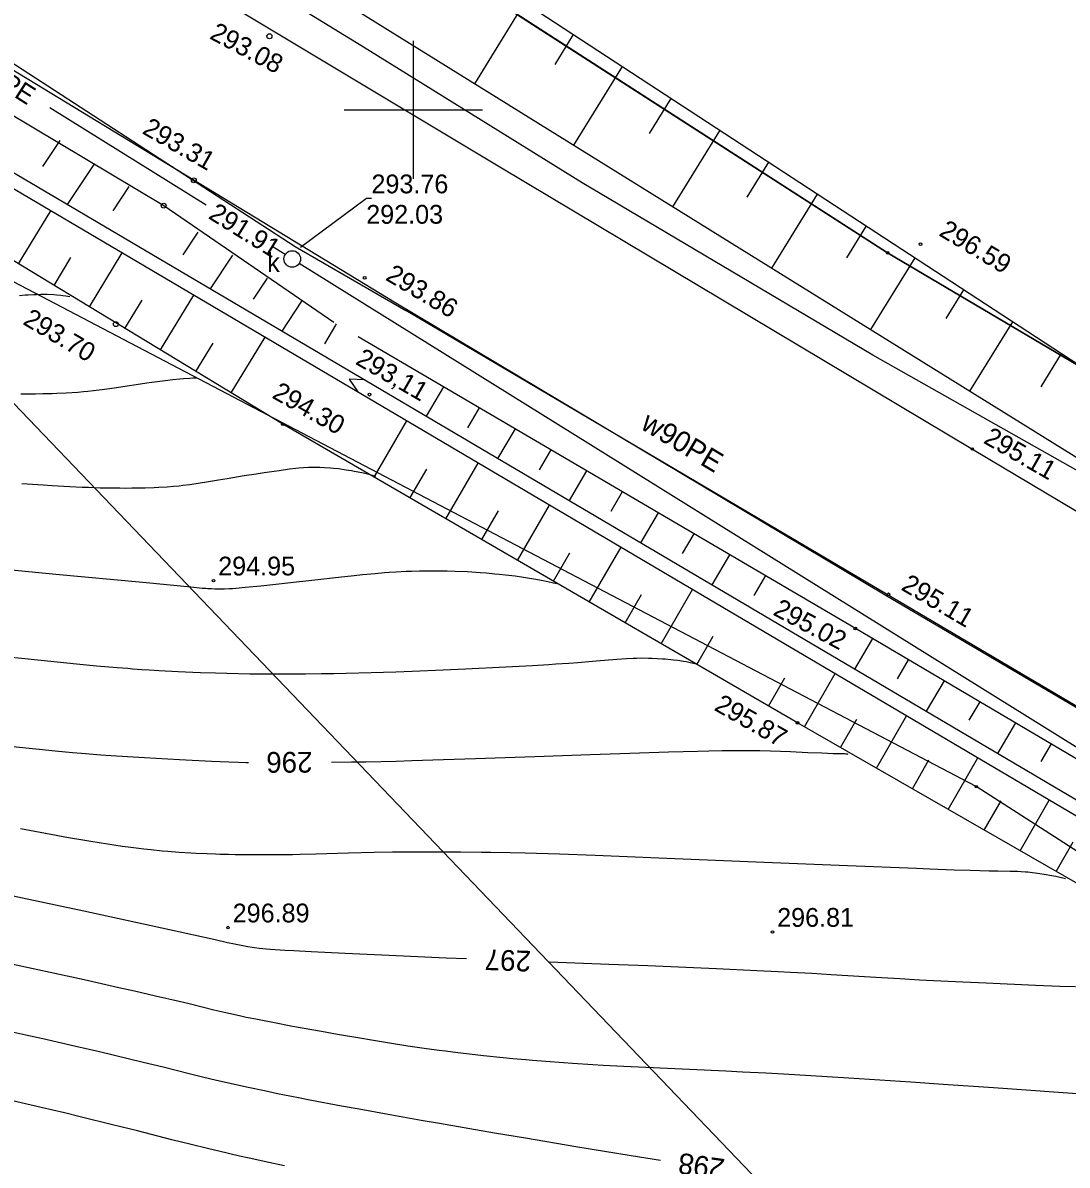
# Model space of a CAD drawing. Extents: x 7477803 to 7478145, y 5500698 to 5500984.
# Drawn here: x 7477935.87 to 7477973.66, y 5500861.83 to 5500903.15 of the extents above; entities that cross this region are included whole.
import ezdxf

# ---------------------------------------------------------------- set-up
doc = ezdxf.new("R2010")
doc.units = 0
for name, color, linetype in [('203-Punkt załamania granicy działki nie stabilizowany', 7, 'Continuous'), ('eNN', 7, 'Continuous'), ('gr_dzialki', 7, 'Continuous'), ('gr_klasy', 7, 'Continuous'), ('jezdnia', 7, 'Continuous'), ('k', 7, 'Continuous'), ('k_elem_naziemne', 7, 'Continuous'), ('k_opis', 7, 'Continuous'), ('k_rzedne', 7, 'Continuous'), ('pkt_wys', 7, 'Continuous'), ('robocza49', 7, 'Continuous'), ('rowy', 7, 'Continuous'), ('skarp_wypel', 7, 'Continuous'), ('skarpa_gora', 7, 'Continuous'), ('w', 7, 'Continuous'), ('w_opis', 7, 'Continuous'), ('warst_ciagla', 7, 'Continuous'), ('warst_opis', 7, 'Continuous'), ('warst_pogrub', 7, 'Continuous'), ('warst_przeryw', 7, 'Continuous')]:
    doc.layers.add(name, color=color, linetype=linetype)

# ---------------------------------------------------------------- blocks, each defined once
blk = doc.blocks.new('203')
blk.add_circle((0, 0), 0.045)
blk = doc.blocks.new('506_5_1')
at = {"layer": 'k_elem_naziemne'}
blk.add_circle((0, 0), 0.3, dxfattribs=at)
blk = doc.blocks.new('801_3')
at = {"layer": 'pkt_wys'}
blk.add_circle((0, 0), 0.045, dxfattribs=at)
blk.add_circle((0, 0), 0.045, dxfattribs=at)
blk = doc.blocks.new('801_5')
at = {"layer": 'pkt_wys'}
blk.add_circle((0, 0), 0.05, dxfattribs=at)
blk.add_circle((0, 0), 0.05, dxfattribs=at)
blk = doc.blocks.new('801_5_4')
at = {"layer": 'pkt_wys'}
blk.add_circle((0, 0), 0.05, dxfattribs=at)
blk.add_circle((0, 0), 0.05, dxfattribs=at)

msp = doc.modelspace()

# ---------------------------------------------------------------- linework, layer by layer
at = {"layer": 'eNN'}
msp.add_lwpolyline([(7478044.292, 5500829.332), (7478043.979, 5500830.08), (7478036.967, 5500842.126), (7478033.374, 5500847.92), (7478030.266, 5500851.792), (7478027.179, 5500855.154), (7478025.031, 5500856.9), (7478008.369, 5500866.572), (7477997.07, 5500873.297), (7477990.438, 5500877.31), (7477980.374, 5500883.358), (7477966.627, 5500891.122), (7477956.111, 5500897.36), (7477948.099, 5500902.324), (7477944.454, 5500904.573)], dxfattribs=at)
at = {"layer": 'gr_dzialki'}
for points in [[(7477967.16, 5500894.83), (7477929.78, 5500918.89)], [(7477970.37, 5500875.52), (7477927.08, 5500898.2)], [(7477995.4, 5500878.14), (7477967.16, 5500894.83)], [(7477983.69, 5500866.96), (7477970.37, 5500875.52)]]:
    msp.add_lwpolyline(points, dxfattribs=at)
at = {"layer": 'gr_klasy'}
for points in [[(7477938.86, 5500913.04), (7477967.16, 5500894.83)], [(7477980.49, 5500842.45), (7477927.08, 5500898.2)], [(7477970.37, 5500875.52), (7477927.08, 5500898.2)], [(7477967.16, 5500894.83), (7477995.4, 5500878.14)], [(7477983.69, 5500866.96), (7477970.37, 5500875.52)]]:
    msp.add_lwpolyline(points, dxfattribs=at)
at = {"layer": 'jezdnia'}
for points in [[(7477987.535, 5500870.412), (7477985.624, 5500871.53), (7477967.072, 5500882.45), (7477949.37, 5500893.011), (7477933.46, 5500902.673), (7477915.126, 5500915.133), (7477901.636, 5500924.498), (7477893.479, 5500930.51)], [(7477941.067, 5500905.192), (7477953.13, 5500897.937)], [(7477953.13, 5500897.937), (7477970.226, 5500887.733), (7477991.46, 5500875.087)]]:
    msp.add_lwpolyline(points, dxfattribs=at)
at = {"layer": 'k'}
for p, q in [((7477942.504, 5500896.548), (7477936.843, 5500900.076)), ((7477945.364, 5500894.765), (7477944.891, 5500895.06)), ((7477986.572, 5500869.11), (7477945.873, 5500894.448))]:
    msp.add_line(p, q, dxfattribs=at)
at = {"layer": 'k_rzedne'}
msp.add_lwpolyline([(7477948.485, 5500896.8), (7477948.305, 5500896.8), (7477945.912, 5500895.027)], dxfattribs=at)
at = {"layer": 'pkt_wys'}
for centre in [(7477944.792, 5500902.663), (7477942.058, 5500897.451), (7477940.967, 5500896.535), (7477939.239, 5500892.249)]:
    msp.add_circle(centre, 0.09, dxfattribs=at)
at = {"layer": 'robocza49'}
for p, q in [((7477950, 5500897.5), (7477950, 5500902.5)), ((7477947.5, 5500900), (7477952.5, 5500900))]:
    msp.add_line(p, q, dxfattribs=at)
at = {"layer": 'rowy'}
for points in [[(7477993.882, 5500863.302), (7477915.697, 5500909.43), (7477904.458, 5500915.769)], [(7477993.629, 5500862.871), (7477915.447, 5500908.997), (7477904.213, 5500915.334)], [(7477948.241, 5500890.23), (7477947.676, 5500890.256), (7477947.987, 5500889.799)]]:
    msp.add_lwpolyline(points, dxfattribs=at)
at = {"layer": 'skarp_wypel'}
for p, q in [((7477954.022, 5500903.878), (7477952.214, 5500900.945)), ((7477955.788, 5500902.724), (7477955.121, 5500901.642)), ((7477957.553, 5500901.57), (7477955.797, 5500898.721)), ((7477959.318, 5500900.416), (7477958.537, 5500899.148)), ((7477961.084, 5500899.262), (7477959.38, 5500896.497)), ((7477937.209, 5500898.89), (7477936.586, 5500897.951)), ((7477938.459, 5500898.061), (7477937.476, 5500896.581)), ((7477962.849, 5500898.108), (7477962.068, 5500896.841)), ((7477939.709, 5500897.231), (7477939.125, 5500896.353)), ((7477964.615, 5500896.954), (7477962.963, 5500894.273)), ((7477935.72, 5500894.431), (7477936.885, 5500896.349)), ((7477966.38, 5500895.8), (7477965.673, 5500894.652)), ((7477942.208, 5500895.572), (7477941.665, 5500894.754)), ((7477937.002, 5500893.653), (7477937.613, 5500894.658)), ((7477938.284, 5500892.874), (7477939.469, 5500894.825)), ((7477943.458, 5500894.743), (7477942.651, 5500893.528)), ((7477968.146, 5500894.646), (7477966.546, 5500892.05)), ((7477944.708, 5500893.913), (7477944.205, 5500893.156)), ((7477940.849, 5500891.317), (7477942.053, 5500893.3)), ((7477969.911, 5500893.492), (7477969.27, 5500892.451)), ((7477939.566, 5500892.096), (7477940.183, 5500893.112)), ((7477945.957, 5500893.084), (7477945.239, 5500892.001)), ((7477947.183, 5500892.212), (7477946.786, 5500891.536)), ((7477947.21, 5500892.259), (7477947.187, 5500892.22)), ((7477971.677, 5500892.338), (7477970.128, 5500889.826)), ((7477943.413, 5500889.76), (7477944.637, 5500891.776)), ((7477942.131, 5500890.539), (7477942.754, 5500891.565)), ((7477973.442, 5500891.184), (7477972.702, 5500889.983)), ((7477951.092, 5500889.983), (7477950.467, 5500888.917)), ((7477952.386, 5500889.224), (7477951.963, 5500888.503)), ((7477948.581, 5500886.712), (7477949.763, 5500888.751)), ((7477953.679, 5500888.465), (7477953.05, 5500887.392)), ((7477954.973, 5500887.706), (7477954.551, 5500886.986)), ((7477951.176, 5500885.207), (7477952.347, 5500887.227)), ((7477949.878, 5500885.96), (7477950.483, 5500887.003)), ((7477956.267, 5500886.947), (7477955.634, 5500885.868)), ((7477957.561, 5500886.188), (7477957.14, 5500885.47)), ((7477952.474, 5500884.455), (7477953.076, 5500885.493)), ((7477953.771, 5500883.702), (7477954.931, 5500885.702)), ((7477958.855, 5500885.429), (7477958.218, 5500884.343)), ((7477960.149, 5500884.67), (7477959.728, 5500883.953)), ((7477955.069, 5500882.95), (7477955.668, 5500883.983)), ((7477956.366, 5500882.197), (7477957.515, 5500884.178)), ((7477961.443, 5500883.911), (7477960.802, 5500882.819)), ((7477962.736, 5500883.152), (7477962.317, 5500882.437)), ((7477958.961, 5500880.692), (7477960.099, 5500882.653)), ((7477957.664, 5500881.445), (7477958.26, 5500882.473)), ((7477960.259, 5500879.94), (7477960.852, 5500880.963)), ((7477966.617, 5500880.874), (7477965.967, 5500879.772)), ((7477967.909, 5500880.112), (7477967.503, 5500879.423)), ((7477962.854, 5500878.435), (7477963.445, 5500879.453)), ((7477964.152, 5500877.683), (7477965.258, 5500879.609)), ((7477969.201, 5500879.35), (7477968.551, 5500878.247)), ((7477970.493, 5500878.588), (7477970.104, 5500877.928)), ((7477966.754, 5500876.189), (7477967.842, 5500878.085)), ((7477965.453, 5500876.936), (7477966.043, 5500877.964)), ((7477971.785, 5500877.826), (7477971.135, 5500876.723)), ((7477973.077, 5500877.064), (7477972.705, 5500876.433)), ((7477968.055, 5500875.443), (7477968.653, 5500876.485)), ((7477969.356, 5500874.696), (7477970.426, 5500876.56)), ((7477970.656, 5500873.949), (7477971.263, 5500875.005)), ((7477971.957, 5500873.202), (7477973.01, 5500875.036)), ((7477973.258, 5500872.455), (7477973.873, 5500873.525))]:
    msp.add_line(p, q, dxfattribs=at)
at = {"layer": 'skarpa_gora'}
msp.add_line((7477947.121, 5500892.308), (7477940.967, 5500896.535), dxfattribs=at)
for points in [[(7478007.879, 5500866.795), (7478009.357, 5500868.166), (7477985.351, 5500883.4), (7477939.898, 5500913.11), (7477944.561, 5500919.785), (7477954.951, 5500928.707), (7477971.014, 5500935.434), (7477981.218, 5500940.405), (7477991.643, 5500944.907), (7477994.866, 5500942.92), (7478002.778, 5500931.769), (7478021.266, 5500905.519), (7478029.289, 5500903.308), (7478032.779, 5500894.332), (7478047.773, 5500881.148)], [(7478007.879, 5500866.795), (7477984.093, 5500881.159), (7477934.83, 5500911.735), (7477933.524, 5500917.153), (7477941.313, 5500926.602), (7477947.253, 5500931.749), (7477948.257, 5500932.619)], [(7477940.967, 5500896.534), (7477905.932, 5500917.459)], [(7478019.361, 5500843.679), (7478014.009, 5500848.521), (7477985, 5500865.71), (7477963.897, 5500877.826), (7477945.275, 5500888.626), (7477927.783, 5500899.247), (7477912.023, 5500908.9), (7477901.238, 5500913.008)], [(7477986.568, 5500869.104), (7477965.993, 5500881.239), (7477948.007, 5500891.789)]]:
    msp.add_lwpolyline(points, dxfattribs=at)
at = {"layer": 'w'}
for points in [[(7477933.012, 5500903.311), (7477945.728, 5500895.058), (7477949.726, 5500892.741)], [(7477987.395, 5500870.305), (7477983.982, 5500872.534), (7477949.726, 5500892.741)]]:
    msp.add_lwpolyline(points, dxfattribs=at)
at = {"layer": 'warst_ciagla'}
for points in [[(7477935.797, 5500889.731), (7477935.978, 5500889.73), (7477936.216, 5500889.73), (7477936.333, 5500889.731), (7477936.595, 5500889.736), (7477936.936, 5500889.745), (7477937.104, 5500889.751), (7477937.433, 5500889.767), (7477937.86, 5500889.795), (7477938.068, 5500889.812), (7477938.221, 5500889.826), (7477938.423, 5500889.847), (7477938.522, 5500889.857), (7477938.743, 5500889.884), (7477939.173, 5500889.942), (7477940.441, 5500890.136), (7477940.825, 5500890.19), (7477941.015, 5500890.214), (7477941.294, 5500890.247), (7477941.557, 5500890.273), (7477941.682, 5500890.284), (7477941.912, 5500890.299), (7477942.016, 5500890.303), (7477942.156, 5500890.305)], [(7477935.4, 5500876.985), (7477936.097, 5500876.91), (7477936.465, 5500876.872), (7477937.046, 5500876.815), (7477937.669, 5500876.758), (7477937.999, 5500876.73), (7477938.696, 5500876.675), (7477939.067, 5500876.648), (7477939.652, 5500876.608), (7477940.27, 5500876.57), (7477940.692, 5500876.546), (7477941.534, 5500876.501), (7477942.696, 5500876.446), (7477943.329, 5500876.419), (7477943.66, 5500876.406), (7477943.956, 5500876.397), (7477944.033, 5500876.396)], [(7477947.033, 5500876.407), (7477947.764, 5500876.414), (7477948.282, 5500876.422), (7477949.376, 5500876.446), (7477949.944, 5500876.461), (7477951.097, 5500876.497), (7477952.247, 5500876.536), (7477954.402, 5500876.615), (7477956.394, 5500876.687), (7477957.482, 5500876.724), (7477959.234, 5500876.779), (7477960.288, 5500876.807), (7477960.694, 5500876.817), (7477961.176, 5500876.826), (7477961.391, 5500876.829), (7477961.814, 5500876.834), (7477962.296, 5500876.833), (7477962.539, 5500876.829), (7477962.921, 5500876.816), (7477963.649, 5500876.786), (7477964.271, 5500876.76), (7477964.786, 5500876.739), (7477965.187, 5500876.724), (7477965.486, 5500876.718), (7477965.6, 5500876.715), (7477965.651, 5500876.71), (7477965.696, 5500876.702), (7477965.716, 5500876.695)], [(7477951.923, 5500869.291), (7477951.188, 5500869.32), (7477949.12, 5500869.409), (7477947.534, 5500869.482), (7477946.3, 5500869.543), (7477945.681, 5500869.577), (7477945.346, 5500869.597), (7477944.828, 5500869.633), (7477944.678, 5500869.645), (7477944.437, 5500869.668), (7477944.257, 5500869.69), (7477944.163, 5500869.703), (7477944.009, 5500869.729), (7477943.588, 5500869.806), (7477943.473, 5500869.829), (7477943.339, 5500869.856), (7477943.281, 5500869.869), (7477942.826, 5500869.974), (7477941.177, 5500870.337), (7477938.073, 5500871.012), (7477936.255, 5500871.406), (7477935.292, 5500871.612)], [(7477973.96, 5500868.276), (7477973.396, 5500868.297), (7477972.513, 5500868.332), (7477970.725, 5500868.408), (7477969.877, 5500868.447), (7477968.818, 5500868.499), (7477968.318, 5500868.525), (7477967.607, 5500868.563), (7477966.728, 5500868.615), (7477966.319, 5500868.64), (7477965.12, 5500868.718), (7477964.414, 5500868.761), (7477963.65, 5500868.802), (7477963.202, 5500868.825), (7477962.424, 5500868.863), (7477960.974, 5500868.929), (7477958.479, 5500869.035), (7477957.078, 5500869.093), (7477954.921, 5500869.177)], [(7477958.937, 5500862.001), (7477957.879, 5500862.172), (7477955.885, 5500862.497), (7477954.061, 5500862.801), (7477952.942, 5500862.99), (7477950.947, 5500863.333), (7477950.284, 5500863.448), (7477949.087, 5500863.66), (7477948.035, 5500863.851), (7477947.4, 5500863.968), (7477946.25, 5500864.186), (7477945.849, 5500864.264), (7477945.336, 5500864.366), (7477945.09, 5500864.415), (7477944.615, 5500864.512), (7477944.021, 5500864.637), (7477943.741, 5500864.698), (7477943.152, 5500864.829), (7477942.879, 5500864.892), (7477942.366, 5500865.014), (7477941.885, 5500865.133), (7477940.952, 5500865.368), (7477940.223, 5500865.548), (7477939.188, 5500865.797), (7477938.644, 5500865.926), (7477937.794, 5500866.122), (7477936.599, 5500866.393), (7477935.974, 5500866.533), (7477935.112, 5500866.722)]]:
    msp.add_lwpolyline(points, dxfattribs=at)
at = {"layer": 'warst_pogrub'}
msp.add_lwpolyline([(7477955.184, 5500882.857), (7477955.023, 5500882.894), (7477954.696, 5500882.963), (7477954.361, 5500883.025), (7477954.136, 5500883.063), (7477953.985, 5500883.086), (7477953.68, 5500883.13), (7477953.336, 5500883.172), (7477953.106, 5500883.197), (7477952.952, 5500883.212), (7477952.646, 5500883.239), (7477952.417, 5500883.257), (7477951.964, 5500883.285), (7477951.519, 5500883.304), (7477951.229, 5500883.312), (7477951.039, 5500883.315), (7477950.668, 5500883.317), (7477950.218, 5500883.312), (7477949.93, 5500883.304), (7477949.744, 5500883.297), (7477949.383, 5500883.279), (7477949.122, 5500883.263), (7477948.952, 5500883.251), (7477948.624, 5500883.224), (7477948.156, 5500883.18), (7477947.859, 5500883.149), (7477947.297, 5500883.086), (7477946.434, 5500882.988), (7477945.447, 5500882.879), (7477945.024, 5500882.833), (7477944.477, 5500882.775), (7477943.911, 5500882.718), (7477943.699, 5500882.699), (7477943.462, 5500882.68), (7477943.345, 5500882.673), (7477943.167, 5500882.667), (7477943.047, 5500882.666), (7477942.891, 5500882.666), (7477942.815, 5500882.668), (7477942.703, 5500882.671), (7477942.559, 5500882.679), (7477942.489, 5500882.684), (7477942.377, 5500882.693), (7477941.947, 5500882.735), (7477940.218, 5500882.9), (7477937.06, 5500883.2), (7477935.215, 5500883.373)], dxfattribs=at)
at = {"layer": 'warst_przeryw'}
for points in [[(7477935.745, 5500893.288), (7477935.952, 5500893.307), (7477936.06, 5500893.314), (7477936.26, 5500893.324), (7477936.362, 5500893.327), (7477936.518, 5500893.33), (7477936.754, 5500893.328), (7477936.987, 5500893.318), (7477937.101, 5500893.31), (7477937.25, 5500893.296), (7477937.321, 5500893.288), (7477937.426, 5500893.273), (7477937.574, 5500893.246)], [(7477948.645, 5500886.742), (7477948.437, 5500886.799), (7477948.295, 5500886.834), (7477948.199, 5500886.856), (7477948.007, 5500886.897), (7477947.862, 5500886.925), (7477947.766, 5500886.942), (7477947.575, 5500886.973), (7477947.296, 5500887.011), (7477947.117, 5500887.03), (7477947.001, 5500887.041), (7477946.782, 5500887.057), (7477946.612, 5500887.065), (7477946.504, 5500887.068), (7477946.304, 5500887.067), (7477946.209, 5500887.064), (7477946.029, 5500887.054), (7477945.858, 5500887.039), (7477945.747, 5500887.027), (7477945.525, 5500886.999), (7477945.141, 5500886.948), (7477944.6, 5500886.87), (7477944.318, 5500886.827), (7477943.88, 5500886.758), (7477943.269, 5500886.658), (7477942.951, 5500886.604), (7477942.513, 5500886.529), (7477942.283, 5500886.492), (7477941.919, 5500886.44), (7477941.661, 5500886.408), (7477941.526, 5500886.394), (7477941.317, 5500886.374), (7477941.097, 5500886.357), (7477940.789, 5500886.338), (7477940.628, 5500886.33), (7477940.293, 5500886.319), (7477939.818, 5500886.311), (7477939.569, 5500886.31), (7477939.377, 5500886.311), (7477939.115, 5500886.313), (7477938.98, 5500886.316), (7477938.671, 5500886.322), (7477938.242, 5500886.336), (7477938.021, 5500886.344), (7477937.566, 5500886.365), (7477936.932, 5500886.399), (7477936.603, 5500886.42), (7477935.834, 5500886.473)], [(7477960.246, 5500879.953), (7477960.022, 5500880.002), (7477959.871, 5500880.03), (7477959.77, 5500880.048), (7477959.568, 5500880.078), (7477959.417, 5500880.097), (7477959.316, 5500880.108), (7477959.117, 5500880.127), (7477959.018, 5500880.135), (7477958.823, 5500880.147), (7477958.633, 5500880.156), (7477958.509, 5500880.159), (7477958.271, 5500880.162), (7477958.079, 5500880.159), (7477957.956, 5500880.156), (7477957.716, 5500880.145), (7477957.363, 5500880.121), (7477956.615, 5500880.055), (7477955.952, 5500880.002), (7477955.624, 5500879.978), (7477955.155, 5500879.947), (7477954.906, 5500879.931), (7477954.315, 5500879.896), (7477953.342, 5500879.843), (7477951.883, 5500879.772), (7477951.085, 5500879.736), (7477949.955, 5500879.689), (7477949.369, 5500879.667), (7477948.475, 5500879.638), (7477947.575, 5500879.613), (7477947.128, 5500879.604), (7477946.683, 5500879.596), (7477946.096, 5500879.59), (7477945.805, 5500879.588), (7477945.227, 5500879.587), (7477944.466, 5500879.591), (7477944.09, 5500879.595), (7477943.254, 5500879.612), (7477942.842, 5500879.623), (7477942.297, 5500879.641), (7477942.027, 5500879.652), (7477941.492, 5500879.675), (7477940.788, 5500879.713), (7477940.44, 5500879.734), (7477940.181, 5500879.751), (7477939.838, 5500879.775), (7477939.668, 5500879.788), (7477939.287, 5500879.817), (7477938.538, 5500879.882), (7477937.807, 5500879.951), (7477936.415, 5500880.093), (7477933.679, 5500880.373)], [(7477973.602, 5500872.19), (7477973.241, 5500872.267), (7477973.029, 5500872.309), (7477972.899, 5500872.332), (7477972.662, 5500872.372), (7477972.504, 5500872.395), (7477972.407, 5500872.407), (7477972.229, 5500872.426), (7477972.148, 5500872.433), (7477971.996, 5500872.443), (7477971.857, 5500872.448), (7477971.597, 5500872.452), (7477971.151, 5500872.459), (7477970.837, 5500872.466), (7477970.148, 5500872.486), (7477969.563, 5500872.505), (7477968.686, 5500872.536), (7477968.206, 5500872.555), (7477965.711, 5500872.657), (7477962.695, 5500872.782), (7477959.167, 5500872.927), (7477957.449, 5500872.997), (7477956.578, 5500873.03), (7477955.289, 5500873.074), (7477954.044, 5500873.11), (7477953.507, 5500873.122), (7477952.808, 5500873.136), (7477952.464, 5500873.141), (7477951.708, 5500873.15), (7477951.339, 5500873.153), (7477950.855, 5500873.155), (7477950.617, 5500873.156), (7477950.148, 5500873.155), (7477949.539, 5500873.151), (7477949.242, 5500873.148), (7477948.588, 5500873.137), (7477947.649, 5500873.114), (7477946.467, 5500873.079), (7477945.903, 5500873.065), (7477945.627, 5500873.059), (7477945.265, 5500873.054), (7477945.086, 5500873.052), (7477944.735, 5500873.049), (7477944.276, 5500873.049), (7477944.052, 5500873.05), (7477943.558, 5500873.056), (7477943.317, 5500873.061), (7477943.002, 5500873.069), (7477942.847, 5500873.074), (7477942.542, 5500873.085), (7477942.146, 5500873.104), (7477941.953, 5500873.114), (7477941.529, 5500873.141), (7477941.12, 5500873.173), (7477940.918, 5500873.191), (7477940.517, 5500873.231), (7477940.246, 5500873.261), (7477940.063, 5500873.283), (7477939.688, 5500873.331), (7477939.469, 5500873.361), (7477939.169, 5500873.404), (7477939.015, 5500873.427), (7477938.7, 5500873.475), (7477938.264, 5500873.545), (7477938.04, 5500873.583), (7477937.518, 5500873.673), (7477936.694, 5500873.823), (7477936.311, 5500873.895), (7477935.785, 5500873.998)], [(7477935.46, 5500869.112), (7477937.023, 5500868.772), (7477938.087, 5500868.539), (7477939.347, 5500868.258), (7477939.91, 5500868.131), (7477940.671, 5500867.958), (7477941.528, 5500867.758), (7477941.889, 5500867.671), (7477942.78, 5500867.452), (7477943.216, 5500867.349), (7477943.714, 5500867.24), (7477943.957, 5500867.188), (7477944.303, 5500867.117), (7477944.486, 5500867.081), (7477944.919, 5500866.996), (7477945.627, 5500866.862), (7477946.68, 5500866.67), (7477947.253, 5500866.569), (7477948.064, 5500866.429), (7477948.486, 5500866.358), (7477949.136, 5500866.253), (7477949.801, 5500866.15), (7477950.137, 5500866.101), (7477950.476, 5500866.053), (7477950.929, 5500865.991), (7477951.158, 5500865.961), (7477951.616, 5500865.904), (7477952.232, 5500865.831), (7477952.542, 5500865.797), (7477953.245, 5500865.724), (7477953.6, 5500865.69), (7477954.075, 5500865.646), (7477954.313, 5500865.626), (7477954.793, 5500865.587), (7477955.437, 5500865.539), (7477955.761, 5500865.517), (7477956.496, 5500865.471), (7477956.866, 5500865.451), (7477957.615, 5500865.413), (7477959.998, 5500865.306), (7477961.306, 5500865.242), (7477961.915, 5500865.21), (7477962.755, 5500865.165), (7477963.187, 5500865.14), (7477964.187, 5500865.082), (7477965.76, 5500864.987), (7477967.995, 5500864.842), (7477969.172, 5500864.763), (7477970.994, 5500864.637), (7477974.521, 5500864.386)], [(7477945.339, 5500861.803), (7477944.776, 5500861.923), (7477944.055, 5500862.08), (7477943.708, 5500862.158), (7477942.959, 5500862.331), (7477942.601, 5500862.416), (7477941.914, 5500862.583), (7477941.259, 5500862.748), (7477940.016, 5500863.065), (7477939.115, 5500863.292), (7477937.947, 5500863.581), (7477937.377, 5500863.72), (7477936.539, 5500863.92), (7477935.454, 5500864.172)]]:
    msp.add_lwpolyline(points, dxfattribs=at)

# ---------------------------------------------------------------- block references
at = {"layer": '203-Punkt załamania granicy działki nie stabilizowany'}
for p in [(7477967.16, 5500894.83), (7477970.37, 5500875.52)]:
    msp.add_blockref('203', p, dxfattribs=at)
at = {"layer": 'k_elem_naziemne', "rotation": 0.0626175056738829}
msp.add_blockref('506_5_1', (7477945.618, 5500894.607), dxfattribs=at)
at = {"layer": 'pkt_wys', "rotation": 0.0626175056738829}
for name, p in [('801_5', (7477968.348, 5500895.141)), ('801_5', (7477948.239, 5500893.929)), ('801_5_4', (7477948.414, 5500889.7)), ('801_3', (7477945.275, 5500888.626)), ('801_3', (7477970.226, 5500887.733)), ('801_3', (7477942.771, 5500882.973)), ('801_3', (7477967.192, 5500882.48)), ('801_5', (7477965.993, 5500881.239)), ('801_5', (7477963.897, 5500877.826)), ('801_3', (7477943.295, 5500870.424)), ('801_3', (7477962.995, 5500870.265))]:
    msp.add_blockref(name, p, dxfattribs=at)

# ---------------------------------------------------------------- texts
at = {"layer": 'k_elem_naziemne'}
msp.add_text('k', height=0.68, rotation=0.0626, dxfattribs=at).set_placement((7477944.712, 5500894.139))
at = {"layer": 'k_opis'}
msp.add_text('ks200PE', height=0.68, rotation=327.424, dxfattribs=at).set_placement((7477932.97, 5500902.118))
at = {"layer": 'k_rzedne'}
for s, rotation, p in [('293.76', 0.0626, (7477948.485, 5500896.98)), ('291.91', 328.0644, (7477942.548, 5500896.095)), ('292.03', 0.0626, (7477948.296, 5500895.88))]:
    msp.add_text(s, height=0.68, rotation=rotation, dxfattribs=at).set_placement(p)
at = {"layer": 'pkt_wys'}
for s, rotation, p in [('293.08', 331.9485, (7477942.593, 5500902.597)), ('293.31', 330.1735, (7477940.153, 5500899.165)), ('296.59', 329.0416, (7477968.98, 5500895.475)), ('293.86', 329.2581, (7477948.956, 5500893.869)), ('293.70', 329.4248, (7477935.836, 5500892.267)), ('293,11', 330.0176, (7477947.868, 5500890.826)), ('294.30', 330.3177, (7477944.851, 5500889.603)), ('295.11', 330.2485, (7477970.591, 5500887.97)), ('294.95', 0.0626, (7477942.94, 5500883.158)), ('295.11', 329.5737, (7477967.613, 5500882.66)), ('295.02', 331.9266, (7477962.978, 5500881.752)), ('295.87', 330.2485, (7477960.848, 5500878.308)), ('296.89', 0.0626, (7477943.464, 5500870.608)), ('296.81', 0.0626, (7477963.164, 5500870.45))]:
    msp.add_text(s, height=0.68, rotation=rotation, dxfattribs=at).set_placement(p)
at = {"layer": 'w_opis'}
msp.add_text('w90PE', height=0.75, rotation=329.1145, dxfattribs=at).set_placement((7477958.182, 5500888.484))
at = {"layer": 'warst_opis'}
for s, rotation, p in [('296', 180.2155, (7477946.352, 5500876.78)), ('297', 177.8333, (7477954.272, 5500869.577)), ('298', 171.8639, (7477961.303, 5500862.042))]:
    msp.add_text(s, height=0.75, rotation=rotation, dxfattribs=at).set_placement(p)

doc.saveas('drawing.dxf')
